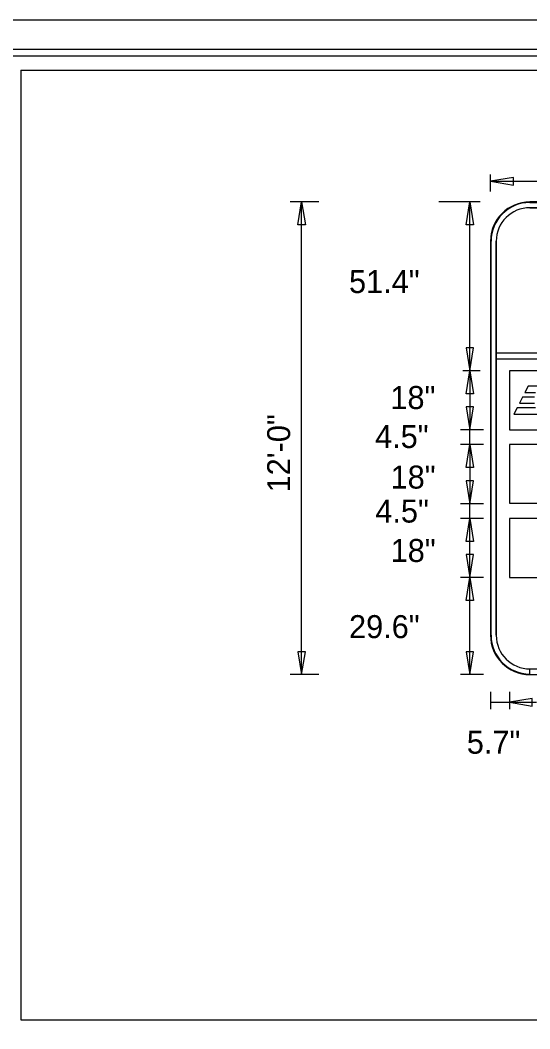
# Model space of a CAD drawing. Extents: x 17890459 to 17890580, y 17897938 to 17898017.
# Drawn here: x 17890480.8 to 17890493.75, y 17897991.76 to 17898017.37 of the extents above; entities that cross this region are included whole.
import ezdxf

# ---------------------------------------------------------------- set-up
doc = ezdxf.new("R2010")
doc.units = 0
for name, color, linetype in [('Default', 7, 'Continuous'), ('GSBWFill', 7, 'Continuous'), ('GSColorFill', 7, 'Continuous'), ('GSDims', 7, 'Continuous'), ('GSOutline', 7, 'Continuous'), ('ImageAttachment_dp', 7, 'Continuous'), ('PlotBorder_dp', 7, 'Continuous'), ('SheetBorder_dp', 7, 'Continuous'), ('SheetLinesMisc2_dp', 7, 'Continuous'), ('SignPanel', 7, 'Continuous')]:
    doc.layers.add(name, color=color, linetype=linetype)

msp = doc.modelspace()

# ---------------------------------------------------------------- linework, layer by layer
at = {"layer": 'Default'}
for points in [[(17890493.975, 17898008.072), (17890493.706, 17898008.072), (17890493.626, 17898007.915), (17890493.897, 17898007.915)], [(17890493.871, 17898007.797), (17890493.566, 17898007.797), (17890493.485, 17898007.639), (17890493.871, 17898007.639)], [(17890493.897, 17898007.521), (17890493.425, 17898007.521), (17890493.345, 17898007.364), (17890493.975, 17898007.364)]]:
    msp.add_lwpolyline(points, dxfattribs=at)
at = {"layer": 'GSBWFill'}
for p, q in [((17890506.251, 17898012.751), (17890493.751, 17898012.751)), ((17890493.751, 17898012.605), (17890506.251, 17898012.605)), ((17890492.751, 17898011.751), (17890492.751, 17898001.751)), ((17890492.897, 17898001.751), (17890492.897, 17898011.751)), ((17890507.105, 17898008.913), (17890492.897, 17898008.913)), ((17890492.897, 17898008.913), (17890492.897, 17898008.768)), ((17890492.897, 17898008.768), (17890507.105, 17898008.768)), ((17890493.751, 17898000.751), (17890493.751, 17898000.896))]:
    msp.add_line(p, q, dxfattribs=at)
for centre, radius, start, end in [((17890493.751, 17898011.751), 1, 90, 180), ((17890493.751, 17898011.751), 0.854, 90, 180), ((17890493.751, 17898001.751), 1, 180, 270), ((17890493.751, 17898001.751), 0.854, 180, 270)]:
    msp.add_arc(centre, radius, start, end, dxfattribs=at)
at = {"layer": 'GSColorFill'}
for p, q in [((17890506.251, 17898012.751), (17890493.751, 17898012.751)), ((17890506.251, 17898012.751), (17890493.751, 17898012.751)), ((17890506.251, 17898012.751), (17890493.751, 17898012.751)), ((17890493.751, 17898012.736), (17890506.251, 17898012.736)), ((17890493.751, 17898012.605), (17890506.251, 17898012.605)), ((17890492.751, 17898011.751), (17890492.751, 17898001.751)), ((17890492.751, 17898011.751), (17890492.751, 17898001.751)), ((17890492.751, 17898011.751), (17890492.751, 17898001.751)), ((17890492.766, 17898001.751), (17890492.766, 17898011.751)), ((17890492.897, 17898001.751), (17890492.897, 17898011.751)), ((17890507.105, 17898008.913), (17890492.897, 17898008.913)), ((17890492.897, 17898008.913), (17890492.897, 17898008.768)), ((17890492.897, 17898008.768), (17890507.105, 17898008.768)), ((17890493.751, 17898000.751), (17890493.751, 17898000.896)), ((17890493.751, 17898000.751), (17890493.751, 17898000.765)), ((17890493.751, 17898000.751), (17890506.251, 17898000.751))]:
    msp.add_line(p, q, dxfattribs=at)
for points in [[(17890493.23, 17898006.966), (17890497.417, 17898006.966), (17890497.417, 17898008.466), (17890493.23, 17898008.466)], [(17890493.23, 17898005.101), (17890497.418, 17898005.101), (17890497.418, 17898006.591), (17890493.23, 17898006.591)]]:
    msp.add_lwpolyline(points, close=True, dxfattribs=at)
for centre, radius, start, end in [((17890493.751, 17898011.751), 1, 90, 180), ((17890493.751, 17898011.751), 1, 90, 180), ((17890493.751, 17898011.751), 1, 90, 180), ((17890493.751, 17898011.751), 0.985, 90, 180), ((17890493.751, 17898011.751), 0.854, 90, 180), ((17890493.751, 17898001.751), 1, 180, 270), ((17890493.751, 17898001.751), 1, 180, 270), ((17890493.751, 17898001.751), 1, 180, 270), ((17890493.751, 17898001.751), 0.985, 180, 270), ((17890493.751, 17898001.751), 0.854, 180, 270)]:
    msp.add_arc(centre, radius, start, end, dxfattribs=at)
at = {"layer": 'GSDims'}
for p, q in [((17890492.751, 17898013.013), (17890492.751, 17898013.451)), ((17890492.751, 17898013.276), (17890507.251, 17898013.276)), ((17890488.388, 17898012.751), (17890487.659, 17898012.751)), ((17890487.951, 17898000.751), (17890487.951, 17898012.751)), ((17890492.489, 17898012.751), (17890491.439, 17898012.751)), ((17890492.489, 17898012.751), (17890491.439, 17898012.751)), ((17890492.489, 17898012.751), (17890492.051, 17898012.751)), ((17890492.226, 17898008.466), (17890492.226, 17898012.751)), ((17890492.489, 17898008.466), (17890492.051, 17898008.466)), ((17890492.226, 17898008.466), (17890492.226, 17898006.966)), ((17890492.576, 17898006.966), (17890491.993, 17898006.966)), ((17890492.226, 17898006.591), (17890492.226, 17898006.966)), ((17890492.226, 17898006.591), (17890492.226, 17898006.966)), ((17890492.226, 17898006.591), (17890492.226, 17898006.966)), ((17890492.226, 17898006.591), (17890492.226, 17898006.966)), ((17890492.576, 17898006.591), (17890491.993, 17898006.591)), ((17890492.226, 17898006.591), (17890492.226, 17898005.091)), ((17890492.576, 17898005.091), (17890491.993, 17898005.091)), ((17890492.576, 17898005.091), (17890491.993, 17898005.091)), ((17890492.576, 17898005.091), (17890491.993, 17898005.091)), ((17890492.576, 17898005.091), (17890491.993, 17898005.091)), ((17890492.576, 17898005.091), (17890491.993, 17898005.091)), ((17890492.576, 17898005.091), (17890491.993, 17898005.091)), ((17890492.576, 17898005.091), (17890491.993, 17898005.091)), ((17890492.576, 17898005.091), (17890491.993, 17898005.091)), ((17890492.576, 17898005.091), (17890491.993, 17898005.091)), ((17890492.576, 17898005.091), (17890491.993, 17898005.091)), ((17890492.226, 17898000.751), (17890492.226, 17898005.091)), ((17890492.576, 17898004.716), (17890491.993, 17898004.716)), ((17890492.576, 17898003.216), (17890491.993, 17898003.216)), ((17890492.576, 17898003.216), (17890491.993, 17898003.216)), ((17890488.388, 17898000.751), (17890487.659, 17898000.751)), ((17890492.576, 17898000.751), (17890491.993, 17898000.751)), ((17890492.751, 17898000.313), (17890492.751, 17897999.876)), ((17890492.751, 17898000.313), (17890492.751, 17897999.876)), ((17890493.23, 17898000.313), (17890493.23, 17897999.876)), ((17890492.751, 17898000.051), (17890493.917, 17898000.051))]:
    msp.add_line(p, q, dxfattribs=at)
for points in [[(17890492.751, 17898013.276), (17890493.334, 17898013.178), (17890493.334, 17898013.373)], [(17890487.951, 17898012.751), (17890488.048, 17898012.167), (17890487.853, 17898012.167)], [(17890492.226, 17898012.751), (17890492.323, 17898012.167), (17890492.129, 17898012.167)], [(17890492.226, 17898008.466), (17890492.323, 17898009.049), (17890492.129, 17898009.049)], [(17890492.226, 17898008.466), (17890492.323, 17898007.883), (17890492.129, 17898007.883)], [(17890492.226, 17898006.966), (17890492.323, 17898007.549), (17890492.129, 17898007.549)], [(17890492.226, 17898006.591), (17890492.323, 17898006.008), (17890492.129, 17898006.008)], [(17890492.226, 17898005.091), (17890492.323, 17898005.674), (17890492.129, 17898005.674)], [(17890492.226, 17898004.716), (17890492.323, 17898004.133), (17890492.129, 17898004.133)], [(17890492.226, 17898003.216), (17890492.323, 17898003.799), (17890492.129, 17898003.799)], [(17890492.226, 17898003.216), (17890492.323, 17898002.633), (17890492.129, 17898002.633)], [(17890487.951, 17898000.751), (17890488.048, 17898001.334), (17890487.853, 17898001.334)], [(17890492.226, 17898000.751), (17890492.323, 17898001.334), (17890492.129, 17898001.334)], [(17890493.23, 17898000.051), (17890493.814, 17897999.953), (17890493.814, 17898000.148)]]:
    msp.add_lwpolyline(points, close=True, dxfattribs=at)
at = {"layer": 'GSOutline'}
for p, q in [((17890506.251, 17898012.751), (17890493.751, 17898012.751)), ((17890506.251, 17898012.605), (17890493.751, 17898012.605)), ((17890492.751, 17898011.751), (17890492.751, 17898001.751)), ((17890492.897, 17898011.751), (17890492.897, 17898001.751)), ((17890507.105, 17898008.913), (17890492.897, 17898008.913)), ((17890492.897, 17898008.913), (17890492.897, 17898008.768)), ((17890492.897, 17898008.768), (17890507.105, 17898008.768)), ((17890493.751, 17898000.896), (17890506.251, 17898000.896)), ((17890493.751, 17898000.751), (17890506.251, 17898000.751))]:
    msp.add_line(p, q, dxfattribs=at)
for centre, radius, start, end in [((17890493.751, 17898011.751), 1, 90, 180), ((17890493.751, 17898011.751), 0.854, 90, 180), ((17890493.751, 17898001.751), 1, 180, 270), ((17890493.751, 17898001.751), 0.854, 180, 270)]:
    msp.add_arc(centre, radius, start, end, dxfattribs=at)
at = {"layer": 'ImageAttachment_dp'}
msp.add_lwpolyline([(17890493.231, 17898003.216), (17890497.417, 17898003.216), (17890497.417, 17898004.716), (17890493.231, 17898004.716)], close=True, dxfattribs=at)
at = {"layer": 'PlotBorder_dp'}
msp.add_lwpolyline([(17890458.908, 17897939.544), (17890580.045, 17897939.544), (17890580.045, 17898017.365), (17890458.908, 17898017.365)], close=True, dxfattribs=at)
at = {"layer": 'SheetBorder_dp'}
msp.add_line((17890462.946, 17898016.631), (17890576.007, 17898016.631), dxfattribs=at)
at = {"layer": 'SheetLinesMisc2_dp'}
for p, q in [((17890463.151, 17898016.456), (17890575.98, 17898016.456)), ((17890463.151, 17898016.456), (17890575.98, 17898016.456)), ((17890480.814, 17898016.097), (17890519.188, 17898016.097)), ((17890480.814, 17898016.097), (17890480.814, 17897991.984)), ((17890480.814, 17897991.984), (17890519.188, 17897991.984))]:
    msp.add_line(p, q, dxfattribs=at)
at = {"layer": 'SignPanel'}
msp.add_line((17890492.897, 17898009.362), (17890492.897, 17898009.362), dxfattribs=at)

# ---------------------------------------------------------------- texts
at = {"layer": 'GSDims'}
for s, p in [('51.4"', (17890489.156, 17898010.438)), ('18"', (17890490.207, 17898007.494)), ('4.5"', (17890489.817, 17898006.504)), ('18"', (17890490.212, 17898005.474)), ('4.5"', (17890489.824, 17898004.611)), ('18"', (17890490.214, 17898003.611)), ('29.6"', (17890489.156, 17898001.678)), ('5.7"', (17890492.149, 17897998.743))]:
    msp.add_text(s, height=0.5833, dxfattribs=at).set_placement(p)
msp.add_text('12\'-0"', height=0.5833, rotation=90, dxfattribs=at).set_placement((17890487.659, 17898005.376))

doc.saveas('drawing.dxf')
